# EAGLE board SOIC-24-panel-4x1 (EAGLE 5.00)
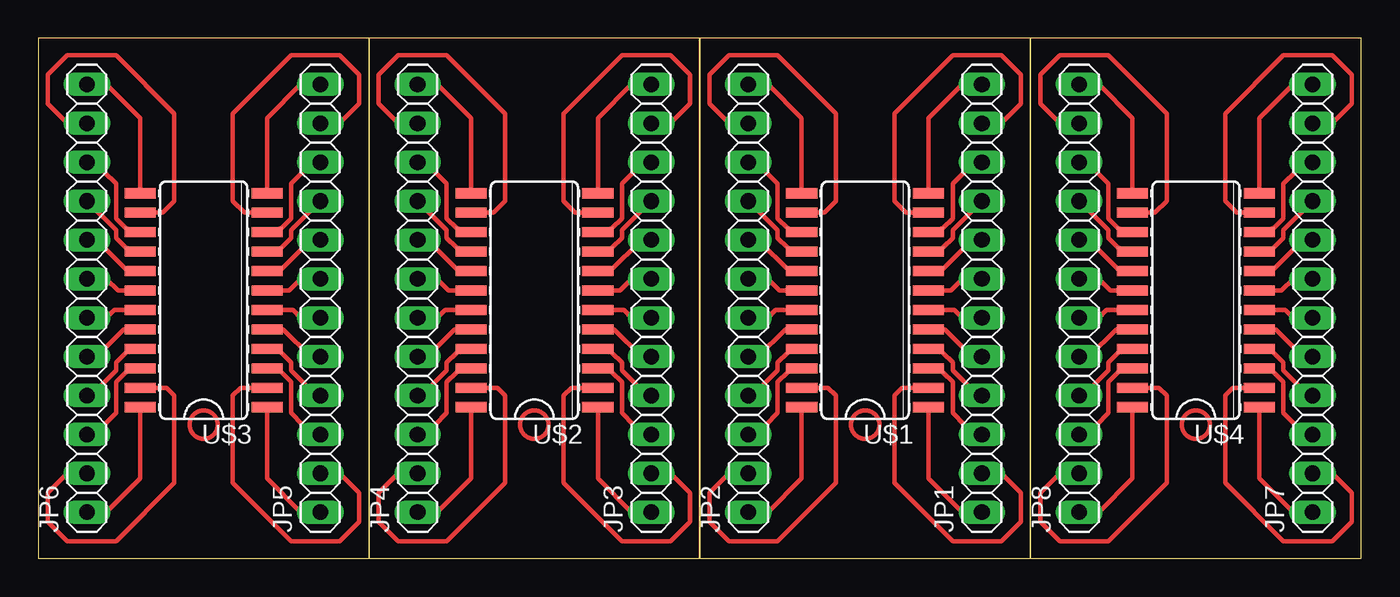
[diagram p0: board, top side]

Size 86.35 x 33.96 mm. Coordinates in mm from the lower left corner, seen from the top.
Outline: 64.76,0 64.76,33.96 43.18,33.96 43.18,0 64.76,0
Outline: 43.17,0 43.17,33.96 21.59,33.96 21.59,0 43.17,0
Outline: 21.58,0 21.58,33.96 0,33.96 0,0 21.58,0
Outline: 86.35,0 86.35,33.96 64.77,33.96 64.77,0 86.35,0
Copper layers (1*16): Top 0.035mm / dielectric 1.5mm / Bottom 0.035mm
Design rules "default": minimum track width 10mil, minimum drill 24mil, track to track 8mil, track to pad 8mil, pad to pad 8mil, via to via 8mil, smd to smd 8mil, copper to edge 40mil, drill to drill 8mil, minimum pad ring 10mil, minimum via ring 8mil, stop-mask expansion 4mil, vias tented up to drill 0mil, thermal gap 10mil

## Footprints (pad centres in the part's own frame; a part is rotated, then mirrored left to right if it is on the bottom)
1X12 = drill 1.016 long: 1 -13.97,0; 2 -11.43,0; 3 -8.89,0; 4 -6.35,0; 5 -3.81,0; 6 -1.27,0; 7 1.27,0; 8 3.81,0; 9 6.35,0; 10 8.89,0; 11 11.43,0; 12 13.97,0
SOIC-24 = smd 0.66 x 2.032: 1 -6.985,-4.14; 2 -5.715,-4.14; 3 -4.445,-4.14; 4 -3.175,-4.14; 5 -1.905,-4.14; 6 -0.635,-4.14; 7 0.635,-4.14; 8 1.905,-4.14; 9 3.175,-4.14; 10 4.445,-4.14; 11 5.715,-4.14; 12 6.985,-4.14; 13 6.985,4.14; 14 5.715,4.14; 15 4.445,4.14; 16 3.175,4.14; 17 1.905,4.14; 18 0.635,4.14; 19 -0.635,4.14; 20 -1.905,4.14; 21 -3.175,4.14; 22 -4.445,4.14; 23 -5.715,4.14; 24 -6.985,4.14

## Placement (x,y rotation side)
JP1  [1X12]  61.59,16.98 90 top
JP2  [1X12]  46.35,16.98 90 top
JP3  [1X12]  40,16.98 90 top
JP4  [1X12]  24.76,16.98 90 top
JP5  [1X12]  18.41,16.98 90 top
JP6  [1X12]  3.17,16.98 90 top
JP7  [1X12]  83.18,16.98 90 top
JP8  [1X12]  67.94,16.98 90 top
U$1  SOIC-24  [SOIC-24]  53.97,16.85 90 top
U$2  SOIC-24  [SOIC-24]  32.38,16.85 90 top
U$3  SOIC-24  [SOIC-24]  10.79,16.85 90 top
U$4  SOIC-24  [SOIC-24]  75.56,16.85 90 top

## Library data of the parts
JP1-JP8 = pinhead
U$1-U$4 = smd

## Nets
N$1: JP1.1 U$1.1
N$2: JP1.2 U$1.2
N$3: JP1.3 U$1.3
N$4: JP1.4 U$1.4
N$5: JP1.5 U$1.5
N$6: JP1.6 U$1.6
N$7: JP1.7 U$1.7
N$8: JP1.8 U$1.8
N$9: JP1.9 U$1.9
N$10: JP1.10 U$1.10
N$11: JP1.11 U$1.11
N$12: JP1.12 U$1.12
N$13: JP2.1 U$1.24
N$14: JP2.2 U$1.23
N$15: JP2.3 U$1.22
N$16: JP2.4 U$1.21
N$17: JP2.5 U$1.20
N$18: JP2.6 U$1.19
N$19: JP2.7 U$1.18
N$20: JP2.8 U$1.17
N$21: JP2.9 U$1.16
N$22: JP2.10 U$1.15
N$23: JP2.11 U$1.14
N$24: JP2.12 U$1.13
N$25: JP3.1 U$2.1
N$26: JP3.2 U$2.2
N$27: JP3.3 U$2.3
N$28: JP3.4 U$2.4
N$29: JP3.5 U$2.5
N$30: JP3.6 U$2.6
N$31: JP3.7 U$2.7
N$32: JP3.8 U$2.8
N$33: JP3.9 U$2.9
N$34: JP3.10 U$2.10
N$35: JP3.11 U$2.11
N$36: JP3.12 U$2.12
N$37: JP4.1 U$2.24
N$38: JP4.2 U$2.23
N$39: JP4.3 U$2.22
N$40: JP4.4 U$2.21
N$41: JP4.5 U$2.20
N$42: JP4.6 U$2.19
N$43: JP4.7 U$2.18
N$44: JP4.8 U$2.17
N$45: JP4.9 U$2.16
N$46: JP4.10 U$2.15
N$47: JP4.11 U$2.14
N$48: JP4.12 U$2.13
N$49: JP5.1 U$3.1
N$50: JP5.2 U$3.2
N$51: JP5.3 U$3.3
N$52: JP5.4 U$3.4
N$53: JP5.5 U$3.5
N$54: JP5.6 U$3.6
N$55: JP5.7 U$3.7
N$56: JP5.8 U$3.8
N$57: JP5.9 U$3.9
N$58: JP5.10 U$3.10
N$59: JP5.11 U$3.11
N$60: JP5.12 U$3.12
N$61: JP6.1 U$3.24
N$62: JP6.2 U$3.23
N$63: JP6.3 U$3.22
N$64: JP6.4 U$3.21
N$65: JP6.5 U$3.20
N$66: JP6.6 U$3.19
N$67: JP6.7 U$3.18
N$68: JP6.8 U$3.17
N$69: JP6.9 U$3.16
N$70: JP6.10 U$3.15
N$71: JP6.11 U$3.14
N$72: JP6.12 U$3.13
N$73: JP7.1 U$4.1
N$74: JP7.2 U$4.2
N$75: JP7.3 U$4.3
N$76: JP7.4 U$4.4
N$77: JP7.5 U$4.5
N$78: JP7.6 U$4.6
N$79: JP7.7 U$4.7
N$80: JP7.8 U$4.8
N$81: JP7.9 U$4.9
N$82: JP7.10 U$4.10
N$83: JP7.11 U$4.11
N$84: JP7.12 U$4.12
N$85: JP8.1 U$4.24
N$86: JP8.2 U$4.23
N$87: JP8.3 U$4.22
N$88: JP8.4 U$4.21
N$89: JP8.5 U$4.20
N$90: JP8.6 U$4.19
N$91: JP8.7 U$4.18
N$92: JP8.8 U$4.17
N$93: JP8.9 U$4.16
N$94: JP8.10 U$4.15
N$95: JP8.11 U$4.14
N$96: JP8.12 U$4.13

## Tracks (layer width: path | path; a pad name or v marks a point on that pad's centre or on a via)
N$1
  Top 0.305: U$1.1 58.11,5.22 60.32,3.01 JP1.1
N$2
  Top 0.305: U$1.2 56.38,11.14 55.88,10.63 55.88,4.92 59.69,1.1 62.86,1.1 64.13,2.38 64.13,4.28 62.86,5.55 JP1.2
N$3
  Top 0.254: 59.05,12.15 U$1.3
  Top 0.305: 59.05,12.15 59.69,11.52 59.69,9.49 60.45,8.73 JP1.3
N$4
  Top 0.254: 59.05,13.42 U$1.4
  Top 0.305: 59.05,13.42 59.69,12.79 59.69,12.28 60.7,11.27 JP1.4
N$5
  Top 0.305: U$1.5 59.18,14.95 60.96,13.17 JP1.5
N$6
  Top 0.305: U$1.6 59.81,16.22 60.32,15.71 JP1.6
N$7
  Top 0.305: U$1.7 59.56,17.49 60.32,18.25 JP1.7
N$8
  Top 0.305: 58.92,18.76 60.96,20.79 JP1.8
  Top 0.406: U$1.8 58.92,18.76
N$9
  Top 0.254: U$1.9 59.05,20.28
  Top 0.305: 59.05,20.28 59.69,20.92 59.69,21.42 JP1.9
N$10
  Top 0.254: 59.05,21.55 U$1.10
  Top 0.305: 59.05,21.55 59.69,22.19 59.69,24.47 60.45,25.23 JP1.10
N$11
  Top 0.305: U$1.11 56.64,22.57 55.88,23.33 55.88,29.04 59.69,32.85 62.86,32.85 64.13,31.58 64.13,29.68 62.86,28.41 JP1.11
N$12
  Top 0.305: U$1.12 58.11,28.74 60.32,30.95 JP1.12
N$13
  Top 0.305: U$1.24 49.83,5.22 47.62,3.01 JP2.1
N$14
  Top 0.305: U$1.23 51.56,11.14 52.07,10.63 52.07,4.92 48.26,1.1 45.08,1.1 43.81,2.38 43.81,4.28 45.08,5.55 JP2.2
N$15
  Top 0.254: U$1.22 48.89,12.15
  Top 0.305: 48.89,12.15 48.26,11.52 48.26,9.49 47.49,8.73 JP2.3
N$16
  Top 0.254: U$1.21 48.89,13.42
  Top 0.305: 48.89,13.42 48.26,12.79 48.26,12.28 47.24,11.27 JP2.4
N$17
  Top 0.305: U$1.20 48.76,14.95 46.98,13.17 JP2.5
N$18
  Top 0.305: U$1.19 48.13,16.22 47.62,15.71 JP2.6
N$19
  Top 0.305: U$1.18 48.38,17.49 47.62,18.25 JP2.7
N$20
  Top 0.305: U$1.17 49.02,18.76 46.98,20.79 JP2.8
N$21
  Top 0.254: U$1.16 48.89,20.28
  Top 0.305: 48.89,20.28 48.26,20.92 48.26,21.42 JP2.9
N$22
  Top 0.254: U$1.15 48.89,21.55
  Top 0.305: 48.89,21.55 48.26,22.19 48.26,24.47 47.49,25.23 JP2.10
N$23
  Top 0.305: U$1.14 51.3,22.57 52.07,23.33 52.07,29.04 48.26,32.85 45.08,32.85 43.81,31.58 43.81,29.68 45.08,28.41
  Top 0.406: 45.08,28.41 JP2.11
N$24
  Top 0.305: U$1.13 49.83,28.74 47.62,30.95 JP2.12
N$25
  Top 0.305: U$2.1 36.52,5.22 38.73,3.01 JP3.1
N$26
  Top 0.305: U$2.2 34.79,11.14 34.29,10.63 34.29,4.92 38.1,1.1 41.27,1.1 42.54,2.38 42.54,4.28 41.27,5.55 JP3.2
N$27
  Top 0.254: 37.46,12.15 U$2.3
  Top 0.305: 37.46,12.15 38.1,11.52 38.1,9.49 38.86,8.73 JP3.3
N$28
  Top 0.254: 37.46,13.42 U$2.4
  Top 0.305: 37.46,13.42 38.1,12.79 38.1,12.28 39.11,11.27 JP3.4
N$29
  Top 0.305: U$2.5 37.59,14.95 39.37,13.17 JP3.5
N$30
  Top 0.305: U$2.6 38.22,16.22 38.73,15.71 JP3.6
N$31
  Top 0.305: U$2.7 37.97,17.49 38.73,18.25 JP3.7
N$32
  Top 0.305: 37.33,18.76 39.37,20.79 JP3.8
  Top 0.406: U$2.8 37.33,18.76
N$33
  Top 0.254: U$2.9 37.46,20.28
  Top 0.305: 37.46,20.28 38.1,20.92 38.1,21.42 JP3.9
N$34
  Top 0.254: 37.46,21.55 U$2.10
  Top 0.305: 37.46,21.55 38.1,22.19 38.1,24.47 38.86,25.23 JP3.10
N$35
  Top 0.305: U$2.11 35.05,22.57 34.29,23.33 34.29,29.04 38.1,32.85 41.27,32.85 42.54,31.58 42.54,29.68 41.27,28.41 JP3.11
N$36
  Top 0.305: U$2.12 36.52,28.74 38.73,30.95 JP3.12
N$37
  Top 0.305: U$2.24 28.24,5.22 26.03,3.01 JP4.1
N$38
  Top 0.305: U$2.23 29.97,11.14 30.47,10.63 30.47,4.92 26.66,1.1 23.49,1.1 22.22,2.38 22.22,4.28 23.49,5.55 JP4.2
N$39
  Top 0.254: U$2.22 27.3,12.15
  Top 0.305: 27.3,12.15 26.66,11.52 26.66,9.49 25.9,8.73 JP4.3
N$40
  Top 0.254: U$2.21 27.3,13.42
  Top 0.305: 27.3,13.42 26.66,12.79 26.66,12.28 25.65,11.27 JP4.4
N$41
  Top 0.305: U$2.20 27.17,14.95 25.39,13.17 JP4.5
N$42
  Top 0.305: U$2.19 26.54,16.22 26.03,15.71 JP4.6
N$43
  Top 0.305: U$2.18 26.79,17.49 26.03,18.25 JP4.7
N$44
  Top 0.305: U$2.17 27.43,18.76 25.39,20.79 JP4.8
N$45
  Top 0.254: U$2.16 27.3,20.28
  Top 0.305: 27.3,20.28 26.66,20.92 26.66,21.42 JP4.9
N$46
  Top 0.254: U$2.15 27.3,21.55
  Top 0.305: 27.3,21.55 26.66,22.19 26.66,24.47 25.9,25.23 JP4.10
N$47
  Top 0.305: U$2.14 29.71,22.57 30.47,23.33 30.47,29.04 26.66,32.85 23.49,32.85 22.22,31.58 22.22,29.68 23.49,28.41
  Top 0.406: 23.49,28.41 JP4.11
N$48
  Top 0.305: U$2.13 28.24,28.74 26.03,30.95 JP4.12
N$49
  Top 0.305: U$3.1 14.93,5.22 17.14,3.01 JP5.1
N$50
  Top 0.305: U$3.2 13.2,11.14 12.7,10.63 12.7,4.92 16.5,1.1 19.68,1.1 20.95,2.38 20.95,4.28 19.68,5.55 JP5.2
N$51
  Top 0.254: 15.87,12.15 U$3.3
  Top 0.305: 15.87,12.15 16.5,11.52 16.5,9.49 17.27,8.73 JP5.3
N$52
  Top 0.254: 15.87,13.42 U$3.4
  Top 0.305: 15.87,13.42 16.5,12.79 16.5,12.28 17.52,11.27 JP5.4
N$53
  Top 0.305: U$3.5 16,14.95 17.77,13.17 JP5.5
N$54
  Top 0.305: U$3.6 16.63,16.22 17.14,15.71 JP5.6
N$55
  Top 0.305: U$3.7 16.38,17.49 17.14,18.25 JP5.7
N$56
  Top 0.305: 15.74,18.76 17.77,20.79 JP5.8
  Top 0.406: U$3.8 15.74,18.76
N$57
  Top 0.254: U$3.9 15.87,20.28
  Top 0.305: 15.87,20.28 16.5,20.92 16.5,21.42 JP5.9
N$58
  Top 0.254: 15.87,21.55 U$3.10
  Top 0.305: 15.87,21.55 16.5,22.19 16.5,24.47 17.27,25.23 JP5.10
N$59
  Top 0.305: U$3.11 13.46,22.57 12.7,23.33 12.7,29.04 16.5,32.85 19.68,32.85 20.95,31.58 20.95,29.68 19.68,28.41 JP5.11
N$60
  Top 0.305: U$3.12 14.93,28.74 17.14,30.95 JP5.12
N$61
  Top 0.305: U$3.24 6.65,5.22 4.44,3.01 JP6.1
N$62
  Top 0.305: U$3.23 8.38,11.14 8.89,10.63 8.89,4.92 5.08,1.1 1.9,1.1 0.63,2.38 0.63,4.28 1.9,5.55 JP6.2
N$63
  Top 0.254: U$3.22 5.71,12.15
  Top 0.305: 5.71,12.15 5.08,11.52 5.08,9.49 4.31,8.73 JP6.3
N$64
  Top 0.254: U$3.21 5.71,13.42
  Top 0.305: 5.71,13.42 5.08,12.79 5.08,12.28 4.06,11.27 JP6.4
N$65
  Top 0.305: U$3.20 5.58,14.95 3.8,13.17 JP6.5
N$66
  Top 0.305: U$3.19 4.95,16.22 4.44,15.71 JP6.6
N$67
  Top 0.305: U$3.18 5.2,17.49 4.44,18.25 JP6.7
N$68
  Top 0.305: U$3.17 5.84,18.76 3.8,20.79 JP6.8
N$69
  Top 0.254: U$3.16 5.71,20.28
  Top 0.305: 5.71,20.28 5.08,20.92 5.08,21.42 JP6.9
N$70
  Top 0.254: U$3.15 5.71,21.55
  Top 0.305: 5.71,21.55 5.08,22.19 5.08,24.47 4.31,25.23 JP6.10
N$71
  Top 0.305: U$3.14 8.12,22.57 8.89,23.33 8.89,29.04 5.08,32.85 1.9,32.85 0.63,31.58 0.63,29.68 1.9,28.41
  Top 0.406: 1.9,28.41 JP6.11
N$72
  Top 0.305: U$3.13 6.65,28.74 4.44,30.95 JP6.12
N$73
  Top 0.305: U$4.1 79.7,5.22 81.91,3.01 JP7.1
N$74
  Top 0.305: U$4.2 77.97,11.14 77.46,10.63 77.46,4.92 81.27,1.1 84.45,1.1 85.72,2.38 85.72,4.28 84.45,5.55 JP7.2
N$75
  Top 0.254: 80.64,12.15 U$4.3
  Top 0.305: 80.64,12.15 81.27,11.52 81.27,9.49 82.04,8.73 JP7.3
N$76
  Top 0.254: 80.64,13.42 U$4.4
  Top 0.305: 80.64,13.42 81.27,12.79 81.27,12.28 82.29,11.27 JP7.4
N$77
  Top 0.305: U$4.5 80.77,14.95 82.55,13.17 JP7.5
N$78
  Top 0.305: U$4.6 81.4,16.22 81.91,15.71 JP7.6
N$79
  Top 0.305: U$4.7 81.15,17.49 81.91,18.25 JP7.7
N$80
  Top 0.305: 80.51,18.76 82.55,20.79 JP7.8
  Top 0.406: U$4.8 80.51,18.76
N$81
  Top 0.254: U$4.9 80.64,20.28
  Top 0.305: 80.64,20.28 81.27,20.92 81.27,21.42 JP7.9
N$82
  Top 0.254: 80.64,21.55 U$4.10
  Top 0.305: 80.64,21.55 81.27,22.19 81.27,24.47 82.04,25.23 JP7.10
N$83
  Top 0.305: U$4.11 78.23,22.57 77.46,23.33 77.46,29.04 81.27,32.85 84.45,32.85 85.72,31.58 85.72,29.68 84.45,28.41 JP7.11
N$84
  Top 0.305: U$4.12 79.7,28.74 81.91,30.95 JP7.12
N$85
  Top 0.305: U$4.24 71.42,5.22 69.21,3.01 JP8.1
N$86
  Top 0.305: U$4.23 73.15,11.14 73.66,10.63 73.66,4.92 69.84,1.1 66.67,1.1 65.4,2.38 65.4,4.28 66.67,5.55 JP8.2
N$87
  Top 0.254: U$4.22 70.48,12.15
  Top 0.305: 70.48,12.15 69.84,11.52 69.84,9.49 69.08,8.73 JP8.3
N$88
  Top 0.254: U$4.21 70.48,13.42
  Top 0.305: 70.48,13.42 69.84,12.79 69.84,12.28 68.83,11.27 JP8.4
N$89
  Top 0.305: U$4.20 70.35,14.95 68.57,13.17 JP8.5
N$90
  Top 0.305: U$4.19 69.72,16.22 69.21,15.71 JP8.6
N$91
  Top 0.305: U$4.18 69.97,17.49 69.21,18.25 JP8.7
N$92
  Top 0.305: U$4.17 70.61,18.76 68.57,20.79 JP8.8
N$93
  Top 0.254: U$4.16 70.48,20.28
  Top 0.305: 70.48,20.28 69.84,20.92 69.84,21.42 JP8.9
N$94
  Top 0.254: U$4.15 70.48,21.55
  Top 0.305: 70.48,21.55 69.84,22.19 69.84,24.47 69.08,25.23 JP8.10
N$95
  Top 0.305: U$4.14 72.89,22.57 73.66,23.33 73.66,29.04 69.84,32.85 66.67,32.85 65.4,31.58 65.4,29.68 66.67,28.41
  Top 0.406: 66.67,28.41 JP8.11
N$96
  Top 0.305: U$4.13 71.42,28.74 69.21,30.95 JP8.12
(copper drawn outside any net)
  shapes: Top circle x4

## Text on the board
_tNames: JP2 | U$1 | JP1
